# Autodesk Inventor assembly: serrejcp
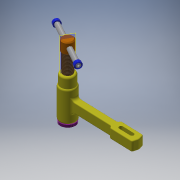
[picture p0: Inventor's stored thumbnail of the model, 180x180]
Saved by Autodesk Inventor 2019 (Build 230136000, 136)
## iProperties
Created: 2019-02
Part Number: serrejcp
Material: Générique
Document SubType Name: Assembly
Designer: si-nd67
Author: si-nd67
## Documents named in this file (6)
- E:\ECAM\serrejointsw\serrejcp.iam
- E:\ECAM\serrejointsw\Mors mobile14C.ipt
- E:\ECAM\serrejointsw\SEB-serrej.iam
- E:\ECAM\serrejointsw\Vis de manoeuvre14.ipt
- E:\ECAM\serrejointsw\Piston14C.ipt
- E:\ECAM\serrejointsw\GoupilleElast112-14.ipt
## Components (5 placed, 5 different names)
1. Mors mobile14C:1 — Axe vis /Mors, Départ, Angle:1, Placage:5, Placage:6, Départ piston
2. SEB-serrej:1 [sub-assembly] — Axe Vis -SEB, Position seb/Vis
3. Vis de manoeuvre14:1 — Axe Vis -SEB, Position seb/Vis, Axe vis /Mors, Départ, Placage:4
4. Piston14C:1 — Placage:4, Angle:1, Départ piston
5. GoupilleElast112-14:1 — Placage:5, Placage:6
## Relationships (9: Mate 6, Insert 2, Angle 1)
- Axe Vis -SEB [Mate]: SEB-serrej:1 ↔ Vis de manoeuvre14:1
- Position seb/Vis [Mate]: SEB-serrej:1 ↔ Vis de manoeuvre14:1
- Axe vis /Mors [Mate]: Mors mobile14C:1 ↔ Vis de manoeuvre14:1
- Départ [Insert]: Mors mobile14C:1 ↔ Vis de manoeuvre14:1
- Placage:4 [Mate]: Vis de manoeuvre14:1 ↔ Piston14C:1
- Angle:1: Mors mobile14C:1 ↔ Piston14C:1
- Placage:5 [Mate]: Mors mobile14C:1 ↔ GoupilleElast112-14:1
- Placage:6 [Mate]: Mors mobile14C:1 ↔ GoupilleElast112-14:1
- Départ piston [Insert]: Mors mobile14C:1 ↔ Piston14C:1
